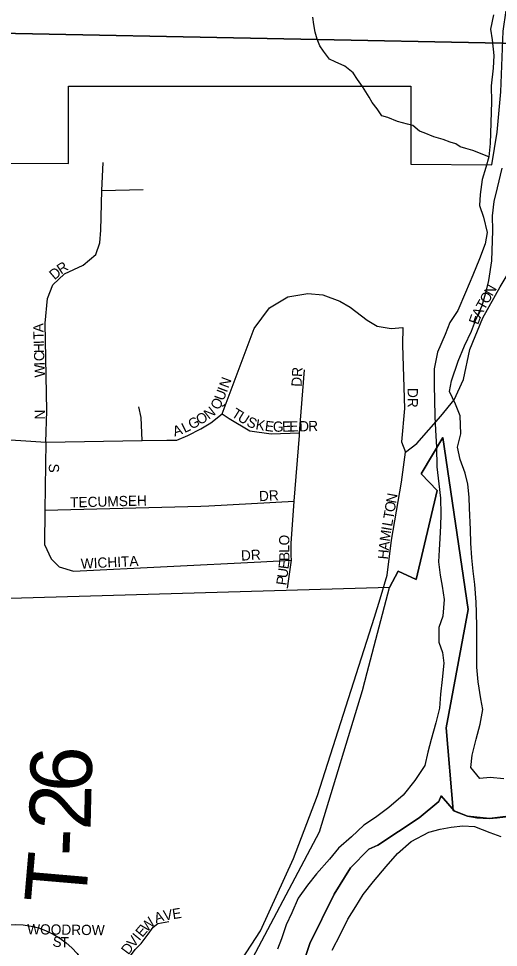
# Model space of a CAD drawing. Extents: x 1310247 to 1552180, y 377264 to 706493.
# Drawn here: x 1389070 to 1391416, y 525062 to 529602 of the extents above; entities that cross this region are included whole.
import ezdxf

# ---------------------------------------------------------------- set-up
doc = ezdxf.new("R2010")
doc.units = 0
for name, color, linetype in [('GM_X_City_Street', 7, 'Continuous'), ('GM_X_City_Street_Text', 7, 'Continuous'), ('GM_X_Corporation', 7, 'Continuous'), ('GM_X_County_Road', 7, 'Continuous'), ('GM_X_Major_River', 7, 'Continuous'), ('GM_X_Minor_River', 7, 'Continuous'), ('GM_X_Section', 7, 'Continuous'), ('GM_X_Township', 7, 'Continuous'), ('GM_X_Township_Road_Text', 7, 'Continuous'), ('GM_X_Township_Subdivision', 7, 'Continuous'), ('GM_X_Township_Subdivision_Text', 7, 'Continuous'), ('GM_X_Unincorporated', 7, 'Continuous')]:
    doc.layers.add(name, color=color, linetype=linetype)

msp = doc.modelspace()

# ---------------------------------------------------------------- linework, layer by layer
at = {"layer": 'GM_X_City_Street'}
for points in [[(1390809.9, 526675.6), (1390838.4, 526764.9), (1390872.4, 526881.4), (1390892.9, 527051.6), (1390941.5, 527336), (1390961.3, 527482.5), (1391017.1, 527523.9), (1391134.6, 527658.3), (1391198.9, 527738.3), (1391244.8, 527837.9), (1391276.4, 527984.4), (1391339.5, 528138.3), (1391424.3, 528291.1), (1391640.1, 528648.7), (1391868, 529016), (1392076.5, 529378.4), (1392295.8, 529737.2), (1392338.5, 529803.9), (1392539.1, 530098.3), (1392662.3, 530285.6)], [(1389202.9, 527530.9), (1389208.9, 527684.9), (1389199.7, 528112.1), (1389211, 528233.4), (1389237.5, 528300.7), (1389294.6, 528353.8), (1389385.3, 528395.6), (1389448.6, 528448.6), (1389467.9, 528504.7), (1389473, 528566.9), (1389477.1, 528761.6), (1389484.3, 528897.6)], [(1389477.1, 528761.6), (1389679.2, 528766.6)], [(1389202.9, 527530.9), (1389202.9, 527530.9), (1389673.6, 527539.2), (1389794.6, 527540.9), (1389844, 527541.4), (1389898.2, 527563.1), (1389961.4, 527595.9), (1390010.1, 527626.3), (1390065.1, 527669.7), (1390222.3, 528087.3), (1390297.1, 528187.1), (1390386.3, 528241.2), (1390483.8, 528257.8), (1390557, 528250.8), (1390641.4, 528220.9), (1390691.6, 528191.5), (1390775, 528127.4), (1390823.2, 528098.4), (1390891.2, 528086.3), (1390949.2, 528092.3), (1390947.3, 528008), (1390947.4, 528005.7)], [(1390947.4, 528005.7), (1390957.3, 527695.7), (1390941.9, 527533.4), (1390961.3, 527482.5)], [(1390442.9, 527564.4), (1390443.9, 527577.2), (1390467.2, 527884.6)], [(1389673.6, 527539.2), (1389669, 527652.2), (1389657.4, 527704)], [(1390065.1, 527669.7), (1390099.1, 527647.4), (1390200.7, 527587.1), (1390304.3, 527572.6), (1390443.9, 527577.2)], [(1390403.4, 526977.2), (1390402.6, 527036.5), (1390417.3, 527243.2), (1390442.9, 527564.4)], [(1388932.1, 527549.2), (1389202.9, 527530.9)], [(1389202.9, 527530.9), (1389198.1, 527198.4), (1389197.2, 527031.4), (1389229.9, 526960.8), (1389268.7, 526922), (1389338.2, 526899.8), (1390253.8, 526946.1), (1390403.6, 526953.7)], [(1389198.1, 527198.4), (1389960.4, 527218.6)], [(1389960.4, 527218.6), (1390000.2, 527219.6), (1390417.3, 527243.2)], [(1390385.4, 526817.8), (1390403.6, 526953.7), (1390403.4, 526977.2)]]:
    msp.add_lwpolyline(points, dxfattribs=at)
at = {"layer": 'GM_X_Corporation'}
for points in [[(1388957.7, 528894.3), (1389314, 528893), (1389314, 529270.8), (1390988.1, 529270.8), (1390988.2, 528889.7), (1391383.7, 528886.9), (1391410.3, 529046.8), (1391427.9, 529243), (1391438.4, 529539.9), (1391468.3, 529743.8), (1391683, 529888.4), (1391872.5, 529923.1), (1392167.5, 530001.1), (1392414.7, 530160.8), (1392641.2, 530294.9), (1396156.9, 529954.2)], [(1391464.4, 525701.4), (1391409.3, 525694.5), (1391372.4, 525691.1), (1391309.7, 525695), (1391294.2, 525697.9), (1391264.6, 525702.9), (1391195.3, 525730.1), (1391161, 526134.6), (1391267.8, 526713.7), (1391143.3, 527554.4), (1391038, 527376.7), (1391115.9, 527294.2), (1391013.2, 526859.5), (1390926.1, 526900.1), (1390883.7, 526821), (1388915.5, 526763.3)], [(1390154.7, 524896.6), (1390540.6, 525626.4), (1390750.8, 526317), (1390774, 526405.8), (1390883.7, 526821), (1390926.1, 526900.1), (1391013.2, 526859.5), (1391115.9, 527294.2), (1391038, 527376.7), (1391143.3, 527554.4), (1391267.8, 526713.7), (1391161, 526134.6), (1391195.3, 525730.1), (1391264.6, 525702.9), (1391294.2, 525697.9), (1391309.7, 525695), (1391372.4, 525691.1), (1391409.3, 525694.5), (1391464.4, 525701.4)]]:
    msp.add_lwpolyline(points, dxfattribs=at)
at = {"layer": 'GM_X_County_Road'}
msp.add_lwpolyline([(1389305.2, 524164), (1389531, 524352.4), (1389864.9, 524665.3), (1390094.4, 524899.9), (1390252.2, 525142.9), (1390413.9, 525495.7), (1390531, 525803.4), (1390809.9, 526675.6)], dxfattribs=at)
at = {"layer": 'GM_X_Major_River'}
for points in [[(1391391.8, 529619.8), (1391377.6, 529550.1), (1391386, 529497.7), (1391393.6, 529421.2), (1391389.7, 529359.2), (1391381, 529273.2), (1391382.6, 529194.9), (1391376.2, 528990.6), (1391368.2, 528926.6), (1391354.6, 528872.9), (1391336.7, 528815.3), (1391326.4, 528741.4), (1391322.7, 528687.4), (1391343, 528630.6), (1391360.7, 528555.8), (1391350.9, 528500), (1391322.6, 528426.7), (1391290.1, 528347.4), (1391255.5, 528262.3), (1391216.7, 528175.2), (1391178.8, 528116.3), (1391155, 528056.8), (1391118.3, 527971.8), (1391101.7, 527890), (1391101.1, 527805.8), (1391103, 527739.6), (1391104.5, 527657.3), (1391108.4, 527589), (1391113.8, 527506.6), (1391114.8, 527410.3), (1391124.2, 527327.8), (1391132.1, 527257.4), (1391133.6, 527179.1), (1391131.9, 527123), (1391129.9, 527060.9), (1391126.2, 527004.9), (1391122.4, 526946.8), (1391130.3, 526880.4), (1391140.7, 526827.9), (1391150.6, 526761.4), (1391144.1, 526681.4), (1391124.4, 526625.9), (1391124.1, 526553.7), (1391142.6, 526503), (1391149, 526450.7), (1391140.4, 526370.7), (1391132.2, 526298.8), (1391128.1, 526230.7), (1391109.8, 526159.1), (1391087.3, 526077.6), (1391071.3, 526015.9), (1391055.3, 525950.2), (1391006.9, 525877.5), (1390950.6, 525805.1), (1390880.7, 525745.1), (1390815.1, 525697), (1390757.9, 525658.7), (1390698.1, 525602.4), (1390634.2, 525546.3), (1390590.6, 525493.5), (1390526.2, 525421.3), (1390482.5, 525366.5), (1390436.4, 525301.8), (1390406.2, 525230.5), (1390378.3, 525171.2), (1390356.2, 525103.8), (1390336.5, 525052.2)], [(1391441.6, 525886), (1391375.8, 525892.1), (1391325.6, 525887.7), (1391281.2, 525941.2), (1391287.1, 526001.2), (1391307.5, 526078.7), (1391325.8, 526152.3), (1391340.1, 526224.1), (1391329.7, 526276.6), (1391316.3, 526359.2), (1391310.5, 526431.6), (1391310.5, 526495.7), (1391310.8, 526569.9), (1391310.6, 526628.1), (1391308.8, 526698.3), (1391306.4, 526748.5), (1391301.1, 526834.9), (1391293.1, 526901.4), (1391285.1, 526965.8), (1391281.4, 527038.1), (1391279.4, 527104.4), (1391274.7, 527208.8), (1391272.4, 527263), (1391266.3, 527325.4), (1391254, 527379.9), (1391228.1, 527446.9), (1391215.9, 527507.4), (1391231.9, 527571.1), (1391228.7, 527659.5), (1391206.4, 527716.3), (1391176.4, 527779.4), (1391186, 527831.3), (1391219, 527926.5), (1391249.4, 528001.8), (1391283.6, 528072.9), (1391303.3, 528126.4), (1391335.6, 528199.6), (1391355.7, 528267.2), (1391369.4, 528320.9), (1391384.4, 528416.7), (1391389, 528565), (1391387.3, 528637.2), (1391395.4, 528707.2), (1391411.6, 528774.9), (1391434.6, 528870.4)], [(1390602.7, 525047.9), (1390643.2, 525126.9), (1390679.5, 525199.9), (1390719.4, 525260.9), (1390755.3, 525319.9), (1390805.4, 525384.5), (1390867.7, 525456.8), (1390921.7, 525521.2), (1390989.6, 525579.3), (1391075.1, 525624.8), (1391131.6, 525639), (1391184, 525649.4), (1391242.3, 525655.6), (1391298.2, 525651.9), (1391373.4, 525623.5), (1391426.8, 525603.8)]]:
    msp.add_lwpolyline(points, dxfattribs=at)
at = {"layer": 'GM_X_Minor_River'}
msp.add_lwpolyline([(1391368.2, 528926.6), (1391290.7, 528957), (1391256.8, 528965.9), (1391229, 528974.6), (1391207.3, 528989.2), (1391179.4, 528997.9), (1391145.7, 529010.7), (1391099.9, 529023.9), (1391052.2, 529043.1), (1391030.4, 529051.7), (1390997, 529078.5), (1390971.1, 529085.2), (1390923.3, 529098.4), (1390875.6, 529117.7), (1390845.8, 529126.4), (1390822.5, 529161), (1390799.2, 529191.6), (1390783.8, 529218), (1390750.9, 529268.9), (1390727.7, 529303.5), (1390706.4, 529336.1), (1390665.1, 529369.1), (1390617.6, 529390.4), (1390589.8, 529403.1), (1390560.7, 529441.8), (1390543.2, 529468.3), (1390530, 529500.6), (1390520.8, 529534.9), (1390513.7, 529573.1), (1390508.5, 529609.3)], dxfattribs=at)
at = {"layer": 'GM_X_Section'}
for points in [[(1394300.1, 534734.1), (1394220.6, 529425.6), (1388972.8, 529529.6), (1389042, 534828.3)], [(1388972.8, 529529.6), (1394220.6, 529425.6), (1394115.4, 525787.8), (1393058, 524239.9), (1388864, 524337.7)]]:
    msp.add_lwpolyline(points, close=True, dxfattribs=at)
at = {"layer": 'GM_X_Township'}
for points in [[(1391517, 525709.5), (1391372.4, 525691.1), (1391264.6, 525702.9), (1391201, 525727.9), (1391136.4, 525802.9), (1391124.3, 525774.7), (1391028, 525695.2), (1390826.1, 525561.5), (1390782.6, 525541.2), (1390693.1, 525450.5), (1390613.5, 525321.4), (1390494.4, 525080.8), (1390451.2, 524955.6)], [(1390451.2, 524955.6), (1390494.4, 525080.8), (1390613.5, 525321.4), (1390693.1, 525450.5), (1390782.6, 525541.2), (1390826.1, 525561.5), (1391028, 525695.2), (1391124.3, 525774.7), (1391136.4, 525802.9), (1391201, 525727.9), (1391264.6, 525702.9), (1391372.4, 525691.1), (1391517, 525709.5)]]:
    msp.add_lwpolyline(points, dxfattribs=at)
at = {"layer": 'GM_X_Township_Subdivision'}
msp.add_lwpolyline([(1389212, 524475), (1389242.8, 524500.1), (1389428.3, 524767.8), (1389639.5, 525050.6), (1389669.8, 525080.9), (1389703.8, 525127.1), (1389728.1, 525161), (1389751.1, 525179.2), (1389804.5, 525187.7)], dxfattribs=at)
at = {"layer": 'GM_X_Unincorporated'}
msp.add_circle((1389052.9, 524781.3), 392.8, dxfattribs=at)

# ---------------------------------------------------------------- texts
at = {"layer": 'GM_X_City_Street_Text'}
for s, rotation, p in [('D', 40.5989, (1389246.3, 528322)), ('R', 34.1952, (1389278.5, 528349.8)), ('N', 60.2602, (1391386, 528241.5)), ('O', 60.247, (1391364.2, 528203.3)), ('T', 60.4161, (1391346.8, 528172.7)), ('E', 70.1955, (1391316.2, 528102.3)), ('A', 63.4643, (1391327.5, 528134)), ('A', 90.9071, (1389192.2, 528068.2)), ('T', 91.8772, (1389193.4, 528033.3)), ('I', 91.8582, (1389194.1, 528011.2)), ('H', 91.8691, (1389195.5, 527967.3)), ('C', 91.8703, (1389196.8, 527927.7)), ('I', 91.8813, (1389197.5, 527905.7)), ('W', 91.8666, (1389199.4, 527848.5)), ('DR', 86.9884, (1390453.4, 527800.9)), ('N', 69.2715, (1390095.5, 527791.9)), ('I', 69.27, (1390087.7, 527771.3)), ('DR', 270, (1390972.3, 527796.1)), ('U', 69.4317, (1390072.2, 527730.2)), ('N', 38.562, (1390000.3, 527640.2)), ('Q', 62.3874, (1390049.1, 527685.1)), ('T', 327.8484, (1390107.1, 527658.8)), ('N', 90, (1389199.4, 527642)), ('O', 30.1092, (1389955.6, 527613.6)), ('U', 327.8255, (1390136.9, 527640)), ('A', 18.0444, (1389833.3, 527558.4)), ('L', 25.9799, (1389882.1, 527574.9)), ('G', 29.2577, (1389916.5, 527591.7)), ('S', 335.3382, (1390180.5, 527613.2)), ('K', 350.6429, (1390226.4, 527594.3)), ('E', 352.9604, (1390272, 527586.8)), ('G', 0.0433, (1390313.6, 527582.1)), ('E', 1.1062, (1390358.6, 527582.1)), ('E', 1.1246, (1390393.9, 527582.8)), ('D', 1.0929, (1390442.2, 527583.7)), ('R', 1.122, (1390486.3, 527584.6)), ('S', 270, (1389218.2, 527426.4)), ('DR', 3.011, (1390246.7, 527242.3)), ('TECUMSEH', 1.5267, (1389322.9, 527211.5)), ('N', 80.1891, (1390915.1, 527229.7)), ('O', 80.1891, (1390907.6, 527186.3)), ('T', 80.185, (1390901.6, 527151.6)), ('I', 80.2287, (1390891.9, 527095.3)), ('L', 80.1693, (1390895.6, 527116.9)), ('O', 88.0544, (1390393, 527025.6)), ('M', 81.3972, (1390884, 527043.3)), ('L', 91.67, (1390394, 526991.3)), ('A', 84.4612, (1390879.9, 527000.2)), ('WICHITA', 2.8644, (1389375.5, 526912.2)), ('DR', 3.0113, (1390158.7, 526951.8)), ('B', 90.291, (1390394.2, 526950.4)), ('H', 84.7353, (1390875.8, 526956.5)), ('E', 82.8328, (1390389.4, 526908.4)), ('U', 82.253, (1390383.4, 526864.2)), ('P', 82.2582, (1390378.7, 526829.4))]:
    msp.add_text(s, height=50, rotation=rotation, dxfattribs=at).set_placement(p)
at = {"layer": 'GM_X_Township_Road_Text'}
for s, rotation, p in [('6', 88.9774, (1389426.6, 525818.9)), ('2', 88.607, (1389422, 525632.1)), ('-', 87.6595, (1389416.8, 525503.6)), ('T', 85.0954, (1389396.7, 525265.4))]:
    msp.add_text(s, height=300, rotation=rotation, dxfattribs=at).set_placement(p)
at = {"layer": 'GM_X_Township_Subdivision_Text'}
for s, rotation, p in [('V', 9.3078, (1389782.2, 525192.3)), ('E', 8.8874, (1389825.5, 525199.4)), ('W', 45.2675, (1389697.1, 525133.8)), ('A', 17.1734, (1389741.9, 525179.7)), ('WOODROW', 359.2489, (1389112.1, 525125.8)), ('E', 49.6521, (1389675, 525107.7)), ('S', 352.9885, (1389234.1, 525067)), ('T', 359.2546, (1389275, 525062.3)), ('V', 50.9835, (1389633.5, 525056.8)), ('I', 50.4183, (1389661.1, 525090.9)), ('D', 52.8984, (1389607.2, 525022.1))]:
    msp.add_text(s, height=50, rotation=rotation, dxfattribs=at).set_placement(p)

doc.saveas('drawing.dxf')
